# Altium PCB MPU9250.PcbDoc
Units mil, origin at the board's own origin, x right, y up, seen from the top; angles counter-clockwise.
Board outline 740.1 x 1060.28 mil, 2 copper layers (Top Layer, Bottom Layer); 21 components, 14 nets, 76 pads, 25 vias.
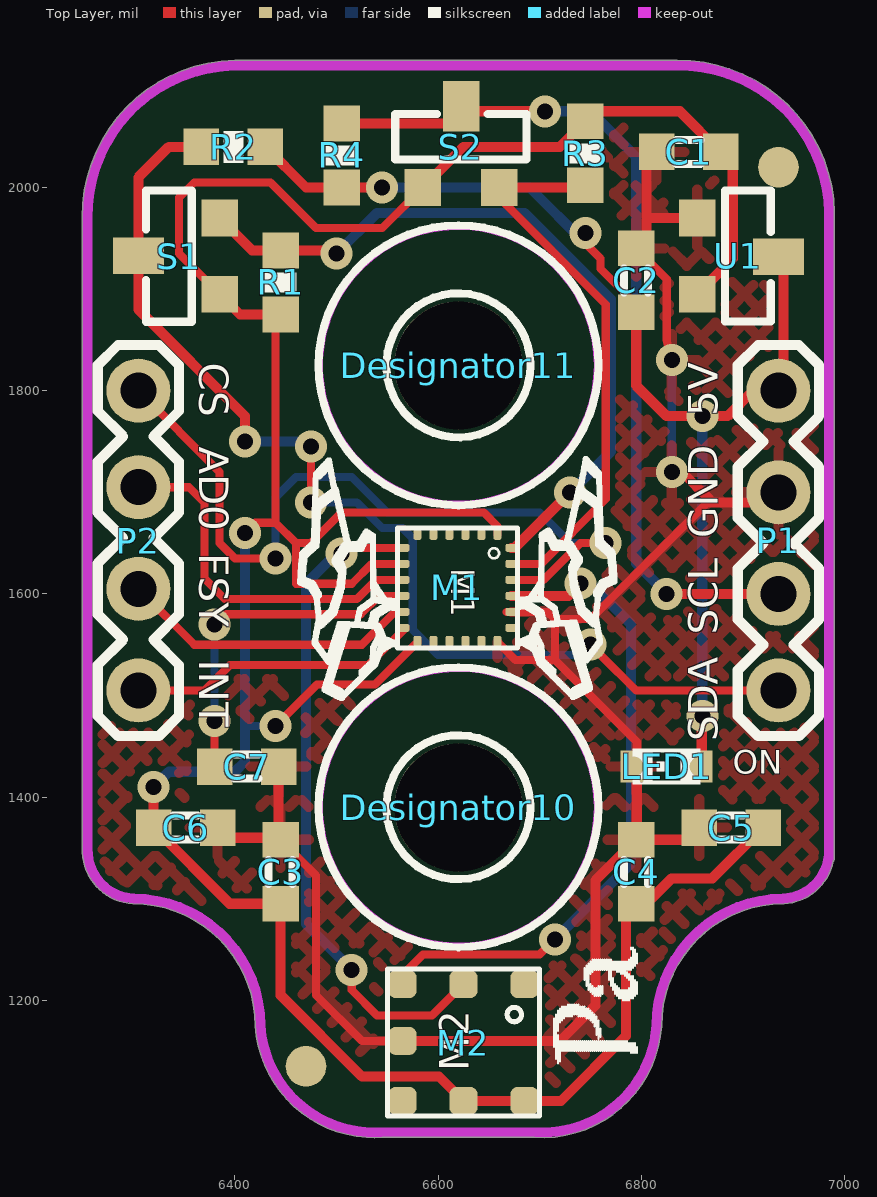
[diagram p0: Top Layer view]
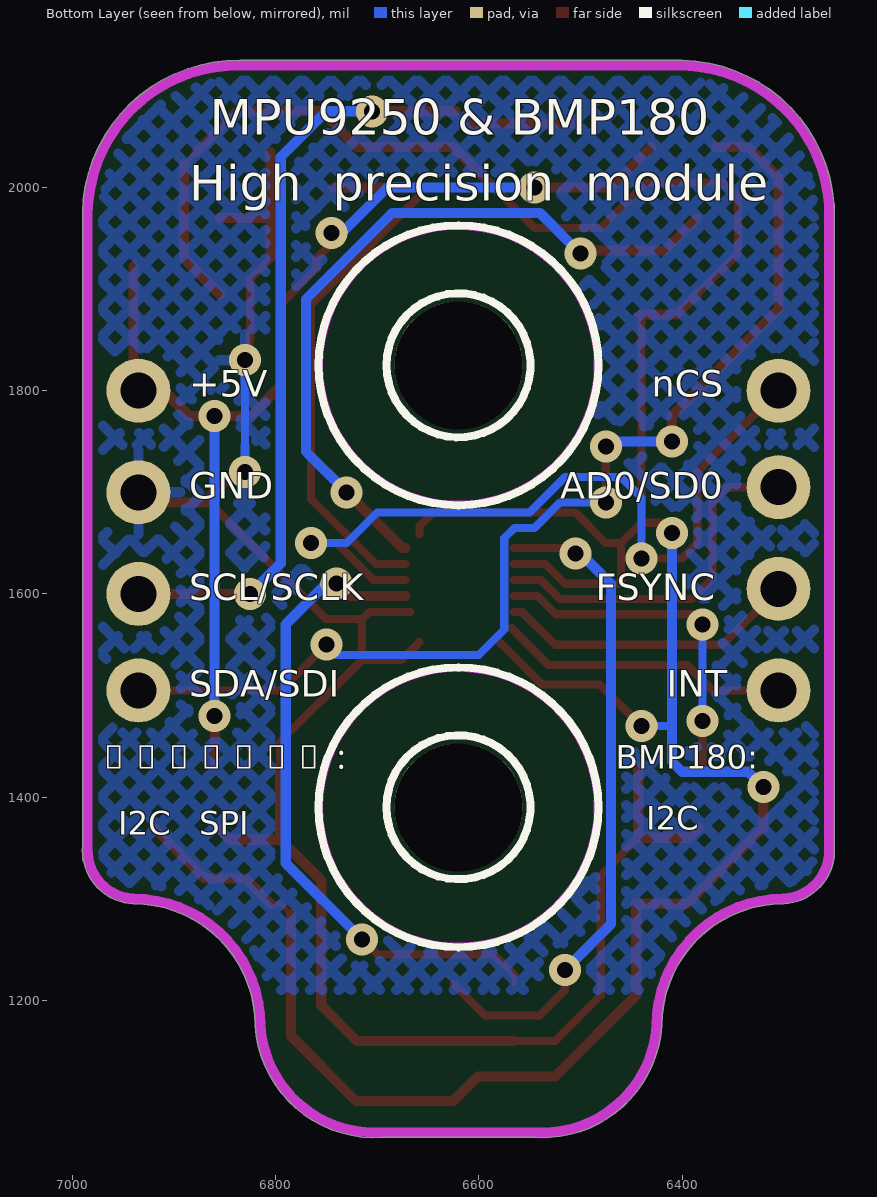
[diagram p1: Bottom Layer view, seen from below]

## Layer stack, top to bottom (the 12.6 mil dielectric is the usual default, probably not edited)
Top Layer: signal copper 1.4
Dielectric: dielectric 12.6, FR-4, Dk 4.8
Bottom Layer: signal copper 1.4

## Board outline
6420,1174.67 cw(c6425,1175) 6419.99,1175 ccw(c6300,1175) 6300,1294.98 cw(c6300,1300) 6299.74,1294.99 cw(c6302.5,1347.5) 6249.98,1350.13 6249.98,1970.57 cw(c6402.5,1972.51) 6399.91,2125.01 cw(c6400,2120) 6400,2125.01 6835.01,2125.01 cw(c6835.01,2120) 6835.23,2125.01 cw(c6837.51,1972.5) 6990.01,1975.09 cw(c6985,1975) 6990.02,1975 6990.02,1350.13 cw(c6937.5,1347.5) 6990.08,1347.5 cw(c6937.5,1347.5) 6990.02,1344.87 6990.02,1340 cw(c6985,1340) 6989.02,1337.01 cw(c6937.5,1347.5) 6940.26,1294.99 cw(c6940,1300) 6940,1294.98 ccw(c6940,1175) 6820.01,1175 cw(c6815,1175) 6820,1174.67 cw(c6702.5,1182.5) 6694.84,1064.98 6545.16,1064.98 cw(c6537.5,1182.5) 6529.67,1065 cw(c6537.5,1182.5)

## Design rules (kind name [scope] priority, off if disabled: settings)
Clearance [All] p1: gap=5
HoleSize [All] p1: absolutevalues=TRUE maxlimit=200 minlimit=1 maxpercent=80.000 minpercent=20.000
HoleToHoleClearance [All] p1: gap=0.39 allowstackedmicrovias=TRUE
MinimumSolderMaskSliver [All] p1: minsoldermaskwidth=0.39
PasteMaskExpansion [All] p1: expansion=1
PolygonConnect [All] p1: connectstyle=Relief reliefconductorwidth=10 reliefentries=4 polygonreliefangle="90 Angle" airgapwidth=10
RoutingVias [All] p1: holewidth=15.75 width=15.75 viastyle="Through Hole" minholewidth=7.87 minwidth=7.87 maxholewidth=35.43 maxwidth=50
SilkToSilkClearance [All] p1: silktosilkclearance=0.39
SilkToSolderMaskClearance [IsPad] p1: minsilkscreentomaskgap=0 clearancetoexposedcopper=TRUE
SolderMaskExpansion [All] p1: expansion=3
Width [All] p1: maxlimit=10 minlimit=0.39 preferedwidth=5
22 further rules are at their usual default settings.

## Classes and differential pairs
component class PS-MPU-9250A: C1 C2 C3 C4 C5 C6 C7 LED1 M1 M2 P1 P2 R1 R2 R3 R4 S1 S2 U1

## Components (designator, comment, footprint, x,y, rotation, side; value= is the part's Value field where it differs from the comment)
C1 "Cap" CAPC_0603 6815,2035 r0 top
C2 "Cap" CAPC_0603 6795,1940 r270 top
C3 "CAP" CAPC_0603 6445,1295 r90 top
C4 "CAP" CAPC_0603 6795,1295 r90 top
C5 "CAP" CAPC_0603 6920,1370 r180 top
C6 "CAP" CAPC_0603 6320,1370 r0 top
C7 "CAP" CAPC_0603 6380,1430 r0 top
Designator10 "Comment" VIA 6620,1390 r0 top
Designator11 "Comment" VIA 6620,1825 r0 top
LED1 "LED" LED_0603 6780,1420 r0 top
M1 "MPU9250" RM-MPU-9250A 6560,1665 r270 top
M2 "bmp180" "LGA 7pin" 6545,1080 r0 top
P1 "Header 4" 4PIN 6935,1650 r180 top
P2 "Header 4" 4PIN 6305,1655 r0 top
R1 "3.3K" RES_0603 6445,1875 r90 top
R2 "3.3K" RES_0603 6430,2040 r180 top
R3 "3.3K" RES_0603 6745,2065 r270 top
R4 "3.3K" RES_0603 6505,2000 r90 top
S1 "SI2302" SOT-23 6385,1895 r90 top
S2 "SI2302" SOT-23 6585,2000 r0 top
U1 "XC6206P332MR" SOT-23 6855,1970 r270 top

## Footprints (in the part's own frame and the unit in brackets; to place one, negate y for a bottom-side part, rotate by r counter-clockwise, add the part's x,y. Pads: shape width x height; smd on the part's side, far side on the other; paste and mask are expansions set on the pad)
4PIN [mm]
  round 1.6 hole 0.9: 1(0,-3.81) 2(0,-1.27) 3(0,1.27) 4(0,3.683)
  silkscreen extent -1.02,-4.95 1.02,4.83
CAPC_0603 [mil]
  rect 35x36 smd: 1(0,0) 2(63,0)
  silkscreen extent 20,-12 43,12
LED_0603 [mm]
  rect 0.8x0.8 smd: 1(1.893,0.254) 2(0.393,0.254)
  silkscreen extent 0.29,-0.2 1.99,0.7
"LGA 7pin" [mm]
  rrect50% 0.7x0.7 smd: 1(0.508,0.532) 2(2.032,0.532) 3(3.556,0.532) 4(3.556,3.453) 5(2.032,3.453) 6(0.508,3.453) 7(0.508,2.032)
  silkscreen extent 0.14,0.15 3.94,3.83
RES_0603 [mil]
  rect 35x36 smd: 1(0,0) 2(63,0)
  silkscreen extent 22,-16 41,16
RM-MPU-9250A [mm]
  rrect50% 0.3x0.2 smd mask+0.05: 1(0.15,2.5) 2(0.15,2.1) 3(0.15,1.7) 4(0.15,1.3) 5(0.15,0.9) 6(0.15,0.5) 13(2.85,0.5) 14(2.85,0.9) 15(2.85,1.3) 16(2.85,1.7) 17(2.85,2.1) 18(2.85,2.5)
  rrect50% 0.2x0.3 smd mask+0.05: 7(0.5,0.15) 8(0.9,0.15) 9(1.3,0.15) 10(1.7,0.15) 11(2.1,0.15) 12(2.5,0.15) 19(2.5,2.85) 20(2.1,2.85) 21(1.7,2.85) 22(1.3,2.85) 23(0.9,2.85) 24(0.5,2.85)
  silkscreen extent 0,0 3,3
SOT-23 [mil]
  rect 36x36 smd: 1(0,0) 2(75,0)
  rect 36x50 smd: 3(38,80)
  silkscreen extent -27,27 102,72
VIA [mm]
  round 3.2 hole 3.2: ""(0,0)
  silkscreen extent -3.5,-3.5 3.5,3.5

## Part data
C1 C2 C3 C4 C5 C6 C7: "Capacitor"
M1: library part Component_1
P1 P2: "Header, 4-Pin"
R1 R2 R3 R4: library part RES2
S1 S2: library part NMOS
U1: library part 662k

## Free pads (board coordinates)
  round 40 smd: 0(6470,1135) 0(6935,2020)

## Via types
v1: diameter 31.5, hole 15.75, Top Layer to Bottom Layer, 25 vias

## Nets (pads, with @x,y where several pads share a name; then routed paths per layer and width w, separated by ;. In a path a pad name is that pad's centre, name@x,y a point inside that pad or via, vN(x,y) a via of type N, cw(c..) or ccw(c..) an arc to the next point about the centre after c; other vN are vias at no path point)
GND: C1.1 C2.1 C3.2 C4.2 C5.2 C6.2 C7.2 LED1.2 M1.18 M1.20 M2.7 P1.2 U1.1 | length 1924.1
  Top Layer w8: C3.2 6480,1323 6480,1205 6525,1160 M2.7 ; M1.18 6676.22,1535 6715,1535 ; M1.20@6667.32,1582.32 M1.20 6707.68,1582.32 6715,1575 6715,1535 ; 6714.75,1575.25 6750.25,1575.25 6867.5,1692.5 ; C2.1 6825,1910 6825,1850 v1(6830,1830) ; LED1.2 6795.47,1454.53 6715,1535
  Top Layer w10: C6.2 6393,1360 6443,1360 C7.2 ; M2.7 6720,1160 6755,1195 6755,1318 C4.2 6845,1358 C5.2 ; C4.2@6795.47,1358.47 LED1.2 ; C2.1@6805,1935 6805,1970 ; C1.1@6805,2035 6805,1970 ; v1(6830,1720) 6840,1720 6867.5,1692.5 ; U1.1 6805,1970 ; 6865,1690 P1.2@6935,1690
  Bottom Layer w8: v1(6830,1720) v1(6830,1830)
NetC1_2: C1.2 C3.1 C4.1 C5.1 C6.1 M1.1 M1.8 M1.13 M2.2 M2.3 R1.1 R3.1 S1.1 S2.1 U1.2 | length 3122.5
  Top Layer w5: R1.1@6440,1875 R1.1 ; M1.13@6579.18,1552.8 M1.13 ; C4.1@6785,1285 C4.1 C4.1@6805,1295 ; C1.2 C1.2@6890,2023
  Top Layer w8: S1.1 6345,1935 6345,1990 6360,2005 6435,2005 6480,1960 6545,1960 S2.1 ; v1(6410,1660) 6420,1670 6440,1670 ; v1(6440,1470) 6480.97,1510.97 6537.86,1510.97 M1.13 ; R1.1@6440,1875 6440,1670 ; M1.8 6534.57,1629.57 6515,1610 6460,1610 6460,1650 ; M1.1 6658.43,1666.57 6645,1680 6505,1680 6475,1650 6460,1650 ; 6440,1670 6460,1650
  Top Layer w10: v1(6320,1410) C6.1 6395,1295 C3.1 6445,1205 6525,1125 6600.94,1125 M2.2 M2.3 6720.94,1100.94 6785,1165 C4.1@6785,1285 ; S1.1 6405,1875 R1.1@6440,1875 ; S2.1 6625,2040 6720,2040 R3.1 6755,2075 6838,2075 C1.2 ; C4.1@6805,1295 6830,1320 6870,1320 C5.1 ; U1.2 6890,1930 C1.2@6890,2023
  Bottom Layer w8: 6410,1470 v1(6440,1470)
  Bottom Layer w10: v1(6320,1410) 6335,1425 6400,1425 6410,1435 6410,1470 v1(6410,1660)
NetC2_2: C2.2 LED1.1 P1.1 R2.1 R4.1 U1.3 | length 1159.4
  Top Layer w5: C2.2 C2.2@6795,1885 ; P1.1@6910,1800 P1.1
  Top Layer w8: v1(6745,1955) 6745,1945 6760,1930 6760,1920 C2.2@6795,1885
  Top Layer w10: R2.1 6470,2000 R4.1 v1(6545,2000) ; C2.2 6795,1805 6825,1775 v1(6860,1775) 6885,1775 P1.1@6910,1800 ; LED1.1@6859.53,1435 v1@6859.53,1479.53 ; P1.1@6940,1800 U1.3@6940,1922
  Bottom Layer w10: v1(6545,2000) 6690,2000 6745,1945 v1(6745,1955) ; v1(6860,1480) v1(6860,1775)
NetC7_1: C7.1 M1.10 | length 337.5
  Top Layer w8: C7.1 v1(6380,1475) ; v1(6380,1570) 6390,1580 6523.86,1580 6541.93,1598.07 M1.10
  Bottom Layer w8: v1(6380,1475) v1(6380,1570)
NetM1_7: M1.7 M2.5 | length 672.3
  Top Layer w5: v1(6505,1640) 6500,1640 v1@6505.31,1645.32
  Top Layer w8: v1@6505.31,1645.32 M1.7 ; v1(6515,1230) 6515,1210 6540,1185 6594.06,1185 M2.5
  Bottom Layer w10: v1(6505,1640) 6500,1640 6470,1610 6470,1275 v1(6515,1230)
NetM1_9: M1.9 P2.3 | length 358.2
  Top Layer w8: P2.3 6355,1705 6370,1690 6370,1615 6390,1595 6520,1595 6538.82,1613.82 M1.9
NetM1_11: M1.11 P2.2 | length 297.1
  Top Layer w8: P2.2 6360,1550 6525,1550 6557.32,1582.32 M1.11
NetM1_12: M1.12 P2.1 | length 288.4
  Top Layer w8: P2.1 6370,1505 6395,1530 6531.3,1530 M1.12@6567.87,1566.57
NetM1_21: M1.21 M2.6 | length 653.9
  Top Layer w5: M2.6 M2.6@6565,1225
  Top Layer w8: M2.6@6565,1225 6585,1245 6700,1245 v1(6715,1260)
  Top Layer w10: M1.21 6728.07,1598.07 v1(6740,1610)
  Bottom Layer w10: v1(6715,1260) 6790,1335 6790,1570 6750,1610 v1(6740,1610)
NetM1_22: M1.22 P2.4 | length 772.3
  Top Layer w8: P2.4 6385,1720 6385,1650 6400,1635 v1(6440,1635) ; M1.22 6703.82,1613.82 6740,1650 v1(6765,1650)
  Bottom Layer w8: v1(6440,1635) 6440,1695 6460,1715 6515,1715 6550,1680 6700,1680 6730,1650 v1(6765,1650)
NetM1_23: M1.23 R3.2 S2.2 | length 552.3
  Top Layer w5: S2.2@6660,1990 S2.2
  Top Layer w8: S2.2@6660,1990 6765,1885 6765,1693.38 6701.18,1629.57 M1.23
  Top Layer w10: S2.2 R3.2@6743,2000
NetM1_24: M1.24 R1.2 S1.2 | length 738.3
  Top Layer w10: S1.2 6417,1938 R1.2 6497,1938 v1(6500,1935) ; M1.24 6675.31,1645.32 v1(6730,1700)
  Bottom Layer w10: v1(6500,1935) 6540,1975 6685,1975 6770,1890 6770,1740 v1(6730,1700)
NetP1_3: P1.3 R4.2 S2.3 | length 844.1
  Top Layer w10: R4.2 S2.3@6606,2063 ; S2.3@6623,2075 v1(6705,2075) ; v1(6825,1600) P1.3
  Bottom Layer w10: v1(6705,2075) 6750,2075 6795,2030 6795,1630 v1(6825,1600)
NetP1_4: P1.4 R2.2 S1.3 | length 1093.5
  Top Layer w8: v1@6475,1680 v1(6475,1690) v1(6475,1745) ; v1@6760,1540 6795,1505 P1.4
  Top Layer w10: R2.2 6335,2040 6305,2010 S1.3 6305,1880 6410,1775 v1(6410,1750)
  Bottom Layer w8: v1(6475,1690) 6520,1690 6545,1665 6565,1665 6575,1655 6575,1565 6600,1540 6740,1540 v1(6750,1550)
  Bottom Layer w10: v1(6410,1750) 6470,1750 v1(6475,1745)
pads on no net: Designator10. Designator11. M1.2 M1.3 M1.4 M1.5 M1.6 M1.14 M1.15 M1.16 M1.17 M1.19 M2.1 M2.4

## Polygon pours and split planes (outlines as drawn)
GND on Top Layer "Top Layer-No Net" (hatched 45Degree grid 20 track 10, remove dead copper, pour order 62): 6225,2150 6225,1050 7000,1050 7000,2150 6225,2150
GND on Bottom Layer "Top Layer-No Net" (hatched 45Degree grid 20 track 10, remove dead copper, pour order 69): 6225,2150 6230,2145.73 6230,1210 7005,1210 7000,1214.27 7000,2150 6225,2150

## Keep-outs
Keep-Out Layer:
  circle w2.5: c6620,1390 r134.54
  circle w2.5: c6620,1825 r134.54
  lines w10: 6255.01,1970.01 cw(c6402.5,1972.51) 6400,2120 6835.01,2120 cw(c6837.51,1972.5) 6985,1975 6985,1340 ; 6255,1972.51 6255,1350 ccw(c6302.5,1347.5) 6300,1300 cw(c6300,1175) 6425,1175 ccw(c6537.5,1182.5) 6545,1070 ; 6530,1070 6705,1070 ; 6695,1070 ccw(c6702.5,1182.5) 6815,1175 cw(c6940,1175) 6940,1300 ccw(c6937.5,1347.5) 6985,1350

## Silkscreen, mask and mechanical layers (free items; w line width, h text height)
Top Overlay:
  drawing of 4112 lines, arcs and shapes, not listed
  text "CS" at 6355,1827.5 h50 r270
  text "5V" at 6885,1775 h50 r90
  text "AD0" at 6355,1745 h50 r270
  text "GND" at 6885,1655 h50 r90
  text "FSY" at 6355,1640 h50 r270
  text "M1" at 6605,1625 h40 r270
  text "SCL" at 6885,1560 h50 r90
  text "INT" at 6355,1535 h50 r270
  text "SDA" at 6885,1455 h50 r90
  text "ON" at 6890,1415 h40
  text "M2" at 6640,1130 h50 r90
Bottom Overlay:
  text "MPU9250 & BMP180" at 6865,2040 h60
  text "High  precision  module" at 6885,1975 h60
  text "nCS" at 6430,1785 h45
  text "+5V" at 6885,1785 h45
  text "AD0/SD0" at 6520,1685 h45
  text "GND" at 6885,1685 h45
  text "FSYNC" at 6485,1585 h45
  text "SCL/SCLK" at 6885,1585 h45
  text "INT" at 6415,1490 h45
  text "SDA/SDI" at 6885,1490 h45
  text "BMP180:" at 6465,1420 h40
  text "MPU9250：" at 6975,1420 h40
  text "I2C" at 6435,1360 h40
  text "SPI" at 6875,1355 h40
  text "I2C" at 6955,1355 h40
Bottom Solder:
  drawing of 6290 lines, arcs and shapes, not listed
